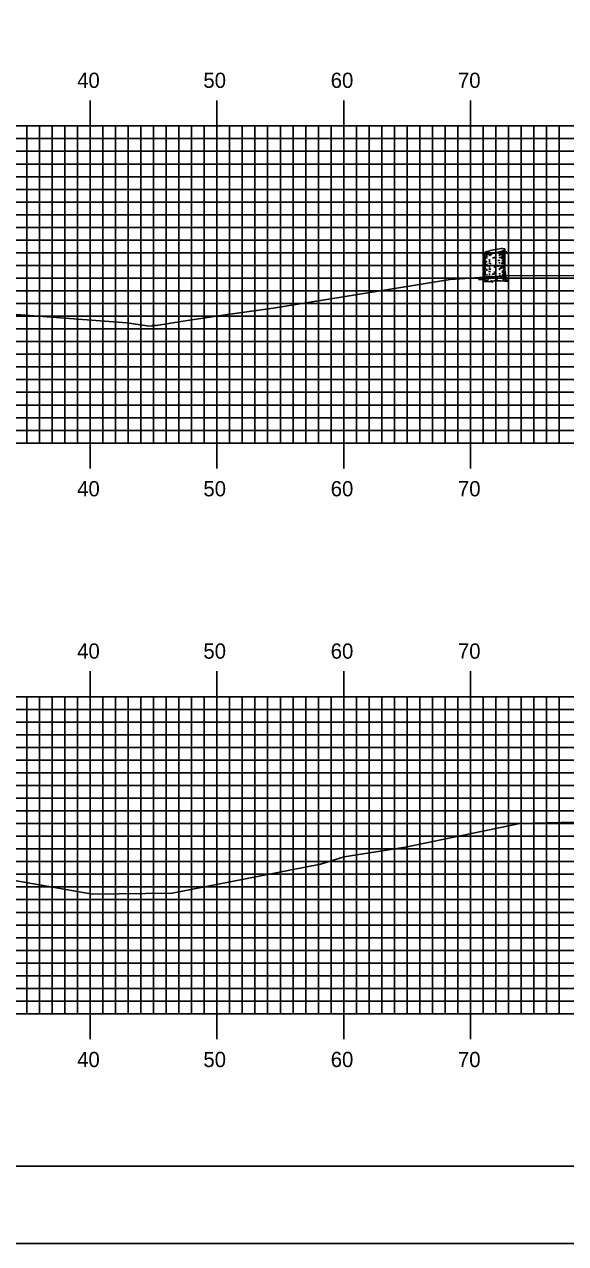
# Model space of a CAD drawing. Extents: x 844143 to 844486, y 363538 to 363758.
# Drawn here: x 844343.3 to 844386, y 363537.6 to 363633.7 of the extents above; entities that cross this region are included whole.
import ezdxf

# ---------------------------------------------------------------- set-up
doc = ezdxf.new("R2010")
doc.units = 0
for name, color, linetype in [('BORDER', 7, 'Continuous'), ('H_V ANNOTATION', 7, 'Continuous'), ('M_Trees_Conifer_Pay', 7, 'Continuous'), ('MAJOR', 7, 'Continuous'), ('MINOR', 7, 'Continuous'), ('PLOT BOUNDARY', 7, 'Continuous'), ('S_Roadway_Centerline', 7, 'Continuous')]:
    doc.layers.add(name, color=color, linetype=linetype)

msp = doc.modelspace()

# ---------------------------------------------------------------- linework, layer by layer
at = {"layer": 'BORDER'}
msp.add_lwpolyline([(844158.85, 363543.721), (844478.85, 363543.721), (844478.85, 363753.721), (844158.85, 363753.721)], close=True, dxfattribs=at)
at = {"layer": 'M_Trees_Conifer_Pay'}
for p, q in [((844379.495, 363613.941), (844379.495, 363615.663)), ((844379.542, 363615.625), (844379.542, 363615.154)), ((844379.6, 363615.614), (844379.6, 363615.516)), ((844379.726, 363615.606), (844379.726, 363615.374)), ((844379.945, 363615.627), (844379.945, 363615.459)), ((844380.741, 363615.669), (844380.741, 363615.469)), ((844380.97, 363615.865), (844380.97, 363615.642)), ((844380.97, 363615.553), (844380.97, 363615.506)), ((844381.087, 363615.926), (844381.087, 363615.763)), ((844381.087, 363615.696), (844381.087, 363615.568)), ((844381.159, 363614.351), (844381.159, 363615.998)), ((844379.542, 363615.09), (844379.542, 363614.781)), ((844379.542, 363614.734), (844379.542, 363614.242)), ((844379.6, 363615.442), (844379.6, 363615.238)), ((844379.6, 363615.18), (844379.6, 363614.981)), ((844379.6, 363614.934), (844379.6, 363614.598)), ((844379.726, 363615.333), (844379.726, 363615.259)), ((844379.726, 363614.856), (844379.726, 363614.717)), ((844379.945, 363615.222), (844379.945, 363614.985)), ((844379.945, 363614.74), (844379.945, 363614.588)), ((844380.351, 363615.395), (844380.351, 363615.3)), ((844380.351, 363614.781), (844380.351, 363614.707)), ((844380.351, 363614.682), (844380.351, 363614.534)), ((844380.741, 363615.411), (844380.741, 363615.323)), ((844380.741, 363614.975), (844380.741, 363614.87)), ((844380.97, 363615.171), (844380.97, 363615.039)), ((844380.97, 363614.928), (844380.97, 363614.818)), ((844380.97, 363614.682), (844380.97, 363614.541)), ((844381.027, 363615.37), (844380.976, 363615.31)), ((844381.087, 363615.381), (844381.087, 363615.045)), ((844381.087, 363615.008), (844381.087, 363614.845)), ((844381.087, 363614.798), (844381.087, 363614.581)), ((844381.087, 363614.551), (844381.087, 363614.476)), ((844379.542, 363614.188), (844379.542, 363613.941)), ((844379.6, 363614.545), (844379.6, 363614.409)), ((844379.6, 363614.31), (844379.6, 363613.931)), ((844379.726, 363614.446), (844379.726, 363614.304)), ((844379.726, 363614.042), (844379.726, 363613.947)), ((844379.726, 363613.548), (844379.888, 363613.612)), ((844379.945, 363614.545), (844379.945, 363614.371)), ((844379.945, 363614.094), (844379.945, 363613.941)), ((844380.351, 363614.242), (844380.351, 363614.089)), ((844380.741, 363614.503), (844380.741, 363614.357)), ((844380.741, 363614.125), (844380.741, 363614.036)), ((844380.97, 363614.314), (844380.97, 363614.141)), ((844381.087, 363614.436), (844381.087, 363614.262)), ((844380.163, 363613.484), (844380.037, 363613.548))]:
    msp.add_line(p, q, dxfattribs=at)
for points in [[(844380.976, 363615.496), (844381.012, 363615.422), (844381.06, 363615.479), (844381.117, 363615.547), (844381.21, 363615.741), (844381.274, 363615.788), (844381.305, 363615.795)], [(844380.99, 363615.243), (844381.027, 363615.37), (844381.09, 363615.486), (844381.121, 363615.553), (844381.19, 363615.699)], [(844381.205, 363615.729), (844381.28, 363615.737), (844381.352, 363615.638)], [(844379.674, 363614.968), (844379.668, 363615.064), (844379.711, 363615.041), (844379.711, 363614.946)], [(844380.813, 363614.57), (844380.825, 363614.493), (844380.873, 363614.503), (844380.86, 363614.67)], [(844380.942, 363615.459), (844380.911, 363615.374), (844380.907, 363615.306), (844380.938, 363615.243)], [(844381.159, 363614.351), (844381.21, 363614.089), (844381.226, 363613.816), (844381.284, 363613.69), (844381.42, 363613.659), (844381.19, 363613.622), (844381.19, 363613.622), (844381.195, 363613.575), (844381.443, 363613.48), (844381.169, 363613.497), (844380.813, 363613.517), (844380.491, 363613.507), (844380.498, 363613.589), (844380.35, 363613.507), (844380.163, 363613.484), (844380.187, 363613.416), (844379.919, 363613.459), (844379.699, 363613.432), (844379.406, 363613.449), (844379.695, 363613.507), (844379.726, 363613.548), (844379.563, 363613.606), (844379.326, 363613.616), (844379.085, 363613.616), (844379.427, 363613.674), (844379.468, 363613.754), (844379.495, 363613.941)], [(844379.543, 363613.894), (844379.522, 363613.816), (844379.501, 363613.721)], [(844379.621, 363613.873), (844379.627, 363613.758), (844379.573, 363613.669), (844379.563, 363613.606)], [(844379.783, 363613.9), (844379.783, 363613.768), (844379.695, 363613.669)], [(844380.01, 363613.659), (844380.077, 363613.754), (844380.104, 363613.894)], [(844380.498, 363613.589), (844380.572, 363613.731), (844380.582, 363613.832)], [(844380.749, 363613.958), (844380.759, 363613.832), (844380.833, 363613.789)], [(844381.027, 363613.569), (844381.012, 363613.707), (844380.938, 363613.836)], [(844380.985, 363614.063), (844381.06, 363613.958), (844381.064, 363613.785), (844381.19, 363613.622)], [(844381.085, 363614.209), (844381.09, 363614.063), (844381.138, 363613.995), (844381.148, 363613.795)]]:
    msp.add_lwpolyline(points, dxfattribs=at)
for centre, radius, start, end in [((844379.526, 363615.661), 0.0314, 156.51582, 169.2194), ((844379.521, 363615.662), 0.0264, 169.2194, 180.03145), ((844379.517, 363615.662), 0.0226, 180.03145, 191.7194), ((844379.517, 363615.662), 0.0226, 191.7194, 203.40735), ((844379.546, 363615.653), 0.0527, 146.7194, 156.51582), ((844379.521, 363615.664), 0.0264, 203.40735, 214.2194), ((844379.525, 363615.667), 0.0314, 214.2194, 226.92298), ((844379.57, 363615.637), 0.0817, 132.38868, 146.7194), ((844379.54, 363615.682), 0.0527, 226.92298, 236.7194), ((844379.555, 363615.707), 0.0817, 236.7194, 251.05013), ((844379.684, 363615.512), 0.251, 124.2194, 132.38868), ((844379.61, 363615.866), 0.251, 251.05013, 259.2194), ((844379.994, 363615.057), 0.802, 108.05939, 124.2194), ((844379.713, 363616.408), 0.802, 259.2194, 275.37941), ((844381.351, 363610.895), 5.179, 101.7194, 108.05939), ((844379.303, 363620.765), 5.179, 275.37941, 281.7194), ((844380.327, 363619.675), 4.124, 264.6955, 266.73309), ((844381.351, 363610.895), 5.179, 95.37941, 101.7194), ((844379.303, 363620.765), 5.179, 281.7194, 288.05939), ((844380.327, 363619.675), 4.124, 276.23804, 278.1032), ((844380.94, 363615.253), 0.802, 79.2194, 95.37941), ((844380.66, 363616.604), 0.802, 288.05939, 304.2194), ((844380.828, 363616.157), 0.571, 278.1032, 284.36665), ((844380.828, 363616.312), 0.571, 284.43166, 292.41325), ((844380.828, 363616.157), 0.571, 297.0237, 300), ((844381.043, 363615.794), 0.251, 71.05013, 79.2194), ((844380.97, 363616.148), 0.251, 304.2194, 312.38868), ((844381.027, 363615.966), 0.172, 300, 311.25059), ((844381.027, 363615.812), 0.172, 300, 311.25059), ((844381.098, 363615.954), 0.0817, 56.7194, 71.05013), ((844381.084, 363616.024), 0.0817, 312.38868, 326.7194), ((844381.099, 363615.884), 0.0624, 311.25059, 330), ((844381.099, 363615.729), 0.0624, 311.25059, 330), ((844381.114, 363615.978), 0.0527, 46.92298, 56.7194), ((844381.129, 363615.994), 0.0314, 34.2194, 46.92298), ((844381.108, 363616.008), 0.0527, 326.7194, 336.51582), ((844381.115, 363615.875), 0.0441, 330, 343.94846), ((844381.115, 363615.72), 0.0441, 330, 343.94846), ((844381.133, 363615.997), 0.0264, 23.40735, 34.2194), ((844381.127, 363615.999), 0.0314, 336.51582, 349.2194), ((844381.136, 363615.998), 0.0226, 11.7194, 23.40735), ((844381.136, 363615.998), 0.0226, 0.03145, 11.7194), ((844381.132, 363615.998), 0.0264, 349.2194, 0.03145), ((844381.126, 363615.872), 0.0334, 343.94846, 354.21506), ((844381.126, 363615.717), 0.0334, 343.94846, 354.21506), ((844379.527, 363615.484), 0.0334, 163.94846, 180), ((844379.527, 363615.484), 0.0334, 180, 196.05154), ((844379.527, 363615.038), 0.0334, 163.94846, 180), ((844379.527, 363615.038), 0.0334, 180, 196.05154), ((844379.527, 363614.828), 0.0334, 163.94846, 180), ((844379.527, 363614.828), 0.0334, 180, 196.05154), ((844379.527, 363614.591), 0.0334, 163.94846, 180), ((844379.527, 363614.591), 0.0334, 180, 196.05154), ((844379.537, 363615.487), 0.0441, 196.05154, 210), ((844379.537, 363615.041), 0.0441, 196.05154, 210), ((844379.537, 363614.831), 0.0441, 196.05154, 210), ((844379.537, 363614.594), 0.0441, 196.05154, 210), ((844379.553, 363615.497), 0.0624, 210, 228.74941), ((844379.553, 363615.05), 0.0624, 210, 228.74941), ((844379.553, 363614.84), 0.0624, 210, 228.74941), ((844379.553, 363614.603), 0.0624, 210, 228.74941), ((844379.625, 363615.579), 0.172, 228.74941, 240), ((844379.625, 363615.132), 0.172, 228.74941, 240), ((844379.625, 363614.922), 0.172, 228.74941, 240), ((844379.625, 363614.686), 0.172, 228.74941, 240), ((844379.825, 363615.924), 0.571, 240, 240.33672), ((844379.825, 363615.477), 0.571, 240, 240.33672), ((844379.825, 363615.267), 0.571, 240, 246.85973), ((844379.826, 363615.713), 0.571, 240, 247.05866), ((844379.825, 363615.924), 0.571, 246.85973, 257.98457), ((844379.825, 363615.267), 0.571, 259.27072, 261.8968), ((844380.325, 363618.785), 4.124, 261.8968, 263.14738), ((844380.325, 363618.995), 4.124, 264.08098, 266.66759), ((844380.325, 363619.442), 4.124, 268.07512, 270), ((844380.325, 363619.442), 4.124, 270, 270.35814), ((844380.325, 363618.785), 4.124, 270, 270.35814), ((844380.325, 363618.785), 4.124, 273.14934, 275.45691), ((844380.327, 363619.231), 4.124, 273.70524, 275.95043), ((844380.325, 363619.442), 4.124, 275.78493, 277.05584), ((844380.325, 363618.995), 4.124, 277.61247, 278.1032), ((844380.826, 363615.477), 0.571, 278.1032, 286.92962), ((844380.828, 363615.713), 0.571, 284.44928, 297.04285), ((844380.826, 363615.477), 0.571, 297.18959, 300), ((844380.826, 363615.267), 0.571, 297.18959, 300), ((844381.025, 363615.132), 0.172, 300, 311.25059), ((844381.025, 363614.922), 0.172, 300, 311.25059), ((844381.098, 363615.05), 0.0624, 311.25059, 330), ((844381.098, 363614.84), 0.0624, 311.25059, 330), ((844381.114, 363615.041), 0.0441, 330, 343.94846), ((844381.114, 363614.831), 0.0441, 330, 343.94846), ((844381.124, 363615.038), 0.0334, 343.94846, 354.21506), ((844381.124, 363614.828), 0.0334, 343.94846, 354.21506), ((844381.125, 363615.273), 0.0334, 343.94846, 354.21506), ((844379.527, 363614.393), 0.0334, 163.94846, 180), ((844379.527, 363614.198), 0.0334, 163.94846, 180), ((844379.527, 363614.198), 0.0334, 180, 196.05154), ((844379.527, 363613.977), 0.0334, 163.94846, 180), ((844379.527, 363613.977), 0.0334, 180, 196.05154), ((844379.537, 363614.201), 0.0441, 196.05154, 210), ((844379.537, 363613.98), 0.0441, 196.05154, 210), ((844379.553, 363614.21), 0.0624, 210, 228.74941), ((844379.553, 363613.989), 0.0624, 210, 228.74941), ((844379.625, 363614.292), 0.172, 228.74941, 240), ((844379.625, 363614.072), 0.172, 228.74941, 240), ((844379.825, 363615.031), 0.571, 240, 246.85973), ((844379.814, 363614.839), 0.571, 241.23686, 248.02677), ((844379.825, 363614.637), 0.571, 240, 246.85973), ((844379.825, 363614.417), 0.571, 240, 244.53138), ((844380.325, 363617.935), 4.124, 262.44379, 263.51202), ((844380.325, 363618.351), 4.124, 263.49906, 265.83975), ((844380.325, 363618.548), 4.124, 264.71603, 266.31934), ((844380.325, 363618.155), 4.124, 267.81166, 270), ((844380.325, 363618.155), 4.124, 270, 270.13279), ((844380.325, 363618.155), 4.124, 275.78493, 276.78961), ((844380.325, 363617.935), 4.124, 277.36842, 278.1032), ((844380.826, 363614.417), 0.571, 278.1032, 281.63703), ((844380.826, 363615.031), 0.571, 285.39827, 297.18959), ((844380.826, 363614.637), 0.571, 288.50673, 297.27208), ((844380.826, 363614.833), 0.571, 289.29072, 300), ((844381.025, 363614.488), 0.172, 300, 311.25059), ((844381.025, 363614.072), 0.172, 300, 311.25059), ((844381.098, 363614.405), 0.0624, 311.25059, 330), ((844381.098, 363613.989), 0.0624, 311.25059, 330), ((844381.114, 363614.396), 0.0441, 330, 343.94846), ((844381.114, 363613.98), 0.0441, 330, 343.94846), ((844381.124, 363614.393), 0.0334, 343.94846, 354.21506), ((844381.124, 363613.977), 0.0334, 343.94846, 354.21506)]:
    msp.add_arc(centre, radius, start, end, dxfattribs=at)
at = {"layer": 'MAJOR'}
for p, q in [((844348.45, 363627.725), (844348.45, 363625.721)), ((844358.45, 363627.725), (844358.45, 363625.721)), ((844368.45, 363627.725), (844368.45, 363625.721)), ((844378.45, 363627.725), (844378.45, 363625.721)), ((844168.45, 363625.721), (844448.45, 363625.721)), ((844168.45, 363625.721), (844448.45, 363625.721)), ((844348.45, 363600.721), (844348.45, 363625.721)), ((844358.45, 363600.721), (844358.45, 363625.721)), ((844368.45, 363600.721), (844368.45, 363625.721)), ((844378.45, 363600.721), (844378.45, 363625.721)), ((844168.45, 363620.721), (844448.45, 363620.721)), ((844168.45, 363615.721), (844448.45, 363615.721)), ((844168.45, 363610.721), (844448.45, 363610.721)), ((844168.45, 363605.721), (844448.45, 363605.721)), ((844168.45, 363600.721), (844448.45, 363600.721)), ((844168.45, 363600.721), (844448.45, 363600.721)), ((844348.45, 363598.717), (844348.45, 363600.721)), ((844358.45, 363598.717), (844358.45, 363600.721)), ((844368.45, 363598.717), (844368.45, 363600.721)), ((844378.45, 363598.717), (844378.45, 363600.721)), ((844348.45, 363582.725), (844348.45, 363580.721)), ((844358.45, 363582.725), (844358.45, 363580.721)), ((844368.45, 363582.725), (844368.45, 363580.721)), ((844378.45, 363582.725), (844378.45, 363580.721)), ((844168.45, 363580.721), (844448.45, 363580.721)), ((844168.45, 363580.721), (844448.45, 363580.721)), ((844348.45, 363555.721), (844348.45, 363580.721)), ((844358.45, 363555.721), (844358.45, 363580.721)), ((844368.45, 363555.721), (844368.45, 363580.721)), ((844378.45, 363555.721), (844378.45, 363580.721)), ((844168.45, 363575.721), (844448.45, 363575.721)), ((844168.45, 363570.721), (844448.45, 363570.721)), ((844168.45, 363565.721), (844448.45, 363565.721)), ((844168.45, 363560.721), (844448.45, 363560.721)), ((844168.45, 363555.721), (844448.45, 363555.721)), ((844168.45, 363555.721), (844448.45, 363555.721)), ((844348.45, 363553.717), (844348.45, 363555.721)), ((844358.45, 363553.717), (844358.45, 363555.721)), ((844368.45, 363553.717), (844368.45, 363555.721)), ((844378.45, 363553.717), (844378.45, 363555.721))]:
    msp.add_line(p, q, dxfattribs=at)
at = {"layer": 'MINOR'}
for p, q in [((844343.45, 363600.721), (844343.45, 363625.721)), ((844344.45, 363600.721), (844344.45, 363625.721)), ((844345.45, 363600.721), (844345.45, 363625.721)), ((844346.45, 363600.721), (844346.45, 363625.721)), ((844347.45, 363600.721), (844347.45, 363625.721)), ((844349.45, 363600.721), (844349.45, 363625.721)), ((844350.45, 363600.721), (844350.45, 363625.721)), ((844351.45, 363600.721), (844351.45, 363625.721)), ((844352.45, 363600.721), (844352.45, 363625.721)), ((844353.45, 363600.721), (844353.45, 363625.721)), ((844354.45, 363600.721), (844354.45, 363625.721)), ((844355.45, 363600.721), (844355.45, 363625.721)), ((844356.45, 363600.721), (844356.45, 363625.721)), ((844357.45, 363600.721), (844357.45, 363625.721)), ((844359.45, 363600.721), (844359.45, 363625.721)), ((844360.45, 363600.721), (844360.45, 363625.721)), ((844361.45, 363600.721), (844361.45, 363625.721)), ((844362.45, 363600.721), (844362.45, 363625.721)), ((844363.45, 363600.721), (844363.45, 363625.721)), ((844364.45, 363600.721), (844364.45, 363625.721)), ((844365.45, 363600.721), (844365.45, 363625.721)), ((844366.45, 363600.721), (844366.45, 363625.721)), ((844367.45, 363600.721), (844367.45, 363625.721)), ((844369.45, 363600.721), (844369.45, 363625.721)), ((844370.45, 363600.721), (844370.45, 363625.721)), ((844371.45, 363600.721), (844371.45, 363625.721)), ((844372.45, 363600.721), (844372.45, 363625.721)), ((844373.45, 363600.721), (844373.45, 363625.721)), ((844374.45, 363600.721), (844374.45, 363625.721)), ((844375.45, 363600.721), (844375.45, 363625.721)), ((844376.45, 363600.721), (844376.45, 363625.721)), ((844377.45, 363600.721), (844377.45, 363625.721)), ((844379.45, 363600.721), (844379.45, 363625.721)), ((844380.45, 363600.721), (844380.45, 363625.721)), ((844381.45, 363600.721), (844381.45, 363625.721)), ((844382.45, 363600.721), (844382.45, 363625.721)), ((844383.45, 363600.721), (844383.45, 363625.721)), ((844384.45, 363600.721), (844384.45, 363625.721)), ((844385.45, 363600.721), (844385.45, 363625.721)), ((844168.45, 363624.721), (844448.45, 363624.721)), ((844168.45, 363623.721), (844448.45, 363623.721)), ((844168.45, 363622.721), (844448.45, 363622.721)), ((844168.45, 363621.721), (844448.45, 363621.721)), ((844168.45, 363619.721), (844448.45, 363619.721)), ((844168.45, 363618.721), (844448.45, 363618.721)), ((844168.45, 363617.721), (844448.45, 363617.721)), ((844168.45, 363616.721), (844448.45, 363616.721)), ((844168.45, 363614.721), (844448.45, 363614.721)), ((844168.45, 363613.721), (844448.45, 363613.721)), ((844168.45, 363612.721), (844448.45, 363612.721)), ((844168.45, 363611.721), (844448.45, 363611.721)), ((844168.45, 363609.721), (844448.45, 363609.721)), ((844168.45, 363608.721), (844448.45, 363608.721)), ((844168.45, 363607.721), (844448.45, 363607.721)), ((844168.45, 363606.721), (844448.45, 363606.721)), ((844168.45, 363604.721), (844448.45, 363604.721)), ((844168.45, 363603.721), (844448.45, 363603.721)), ((844168.45, 363602.721), (844448.45, 363602.721)), ((844168.45, 363601.721), (844448.45, 363601.721)), ((844343.45, 363555.721), (844343.45, 363580.721)), ((844344.45, 363555.721), (844344.45, 363580.721)), ((844345.45, 363555.721), (844345.45, 363580.721)), ((844346.45, 363555.721), (844346.45, 363580.721)), ((844347.45, 363555.721), (844347.45, 363580.721)), ((844349.45, 363555.721), (844349.45, 363580.721)), ((844350.45, 363555.721), (844350.45, 363580.721)), ((844351.45, 363555.721), (844351.45, 363580.721)), ((844352.45, 363555.721), (844352.45, 363580.721)), ((844353.45, 363555.721), (844353.45, 363580.721)), ((844354.45, 363555.721), (844354.45, 363580.721)), ((844355.45, 363555.721), (844355.45, 363580.721)), ((844356.45, 363555.721), (844356.45, 363580.721)), ((844357.45, 363555.721), (844357.45, 363580.721)), ((844359.45, 363555.721), (844359.45, 363580.721)), ((844360.45, 363555.721), (844360.45, 363580.721)), ((844361.45, 363555.721), (844361.45, 363580.721)), ((844362.45, 363555.721), (844362.45, 363580.721)), ((844363.45, 363555.721), (844363.45, 363580.721)), ((844364.45, 363555.721), (844364.45, 363580.721)), ((844365.45, 363555.721), (844365.45, 363580.721)), ((844366.45, 363555.721), (844366.45, 363580.721)), ((844367.45, 363555.721), (844367.45, 363580.721)), ((844369.45, 363555.721), (844369.45, 363580.721)), ((844370.45, 363555.721), (844370.45, 363580.721)), ((844371.45, 363555.721), (844371.45, 363580.721)), ((844372.45, 363555.721), (844372.45, 363580.721)), ((844373.45, 363555.721), (844373.45, 363580.721)), ((844374.45, 363555.721), (844374.45, 363580.721)), ((844375.45, 363555.721), (844375.45, 363580.721)), ((844376.45, 363555.721), (844376.45, 363580.721)), ((844377.45, 363555.721), (844377.45, 363580.721)), ((844379.45, 363555.721), (844379.45, 363580.721)), ((844380.45, 363555.721), (844380.45, 363580.721)), ((844381.45, 363555.721), (844381.45, 363580.721)), ((844382.45, 363555.721), (844382.45, 363580.721)), ((844383.45, 363555.721), (844383.45, 363580.721)), ((844384.45, 363555.721), (844384.45, 363580.721)), ((844385.45, 363555.721), (844385.45, 363580.721)), ((844168.45, 363579.721), (844448.45, 363579.721)), ((844168.45, 363578.721), (844448.45, 363578.721)), ((844168.45, 363577.721), (844448.45, 363577.721)), ((844168.45, 363576.721), (844448.45, 363576.721)), ((844168.45, 363574.721), (844448.45, 363574.721)), ((844168.45, 363573.721), (844448.45, 363573.721)), ((844168.45, 363572.721), (844448.45, 363572.721)), ((844168.45, 363571.721), (844448.45, 363571.721)), ((844168.45, 363569.721), (844448.45, 363569.721)), ((844168.45, 363568.721), (844448.45, 363568.721)), ((844168.45, 363567.721), (844448.45, 363567.721)), ((844168.45, 363566.721), (844448.45, 363566.721)), ((844168.45, 363564.721), (844448.45, 363564.721)), ((844168.45, 363563.721), (844448.45, 363563.721)), ((844168.45, 363562.721), (844448.45, 363562.721)), ((844168.45, 363561.721), (844448.45, 363561.721)), ((844168.45, 363559.721), (844448.45, 363559.721)), ((844168.45, 363558.721), (844448.45, 363558.721)), ((844168.45, 363557.721), (844448.45, 363557.721)), ((844168.45, 363556.721), (844448.45, 363556.721))]:
    msp.add_line(p, q, dxfattribs=at)
at = {"layer": 'PLOT BOUNDARY'}
msp.add_lwpolyline([(844142.664, 363537.603), (844482.664, 363537.603), (844482.664, 363757.603), (844142.664, 363757.603)], close=True, dxfattribs=at)
at = {"layer": 'S_Roadway_Centerline'}
for points in [[(844285.11, 363616.862), (844289.276, 363616.87), (844300.655, 363616.861), (844301.219, 363616.847), (844301.372, 363616.842), (844302.344, 363616.802), (844303.974, 363616.728), (844312.933, 363616.389), (844317.969, 363616.148), (844321.674, 363615.48), (844322.761, 363615.244), (844340.853, 363610.977), (844351.335, 363610.201), (844352.946, 363609.972), (844353.329, 363609.949), (844353.335, 363609.98), (844353.674, 363609.984), (844355.793, 363610.329), (844359.11, 363610.818), (844362.894, 363611.365), (844376.838, 363613.615), (844381.112, 363613.913), (844387.785, 363613.939)], [(844277.253, 363571.913), (844287.976, 363572.308), (844288.699, 363572.337), (844299.814, 363572.345), (844300.456, 363572.348), (844301.703, 363572.351), (844301.931, 363572.329), (844309.784, 363572.079), (844310.696, 363572.043), (844318.775, 363571.615), (844319.138, 363571.502), (844323.619, 363570.934), (844330.951, 363569.372), (844342.48, 363566.232), (844348.642, 363565.15), (844354.919, 363565.244), (844366.62, 363567.514), (844368.496, 363568.092), (844373.315, 363568.864), (844382.329, 363570.725), (844386.68, 363570.832)]]:
    msp.add_lwpolyline(points, dxfattribs=at)

# ---------------------------------------------------------------- texts
at = {"layer": 'H_V ANNOTATION'}
for s, p in [('40', (844347.423, 363628.721)), ('50', (844357.38, 363628.721)), ('60', (844367.423, 363628.721)), ('70', (844377.455, 363628.721)), ('40', (844347.423, 363596.521)), ('50', (844357.38, 363596.521)), ('60', (844367.423, 363596.521)), ('70', (844377.455, 363596.521)), ('40', (844347.423, 363583.721)), ('50', (844357.38, 363583.721)), ('60', (844367.423, 363583.721)), ('70', (844377.455, 363583.721)), ('40', (844347.423, 363551.521)), ('50', (844357.38, 363551.521)), ('60', (844367.423, 363551.521)), ('70', (844377.455, 363551.521))]:
    msp.add_text(s, height=1.2, dxfattribs=at).set_placement(p)

doc.saveas('drawing.dxf')
